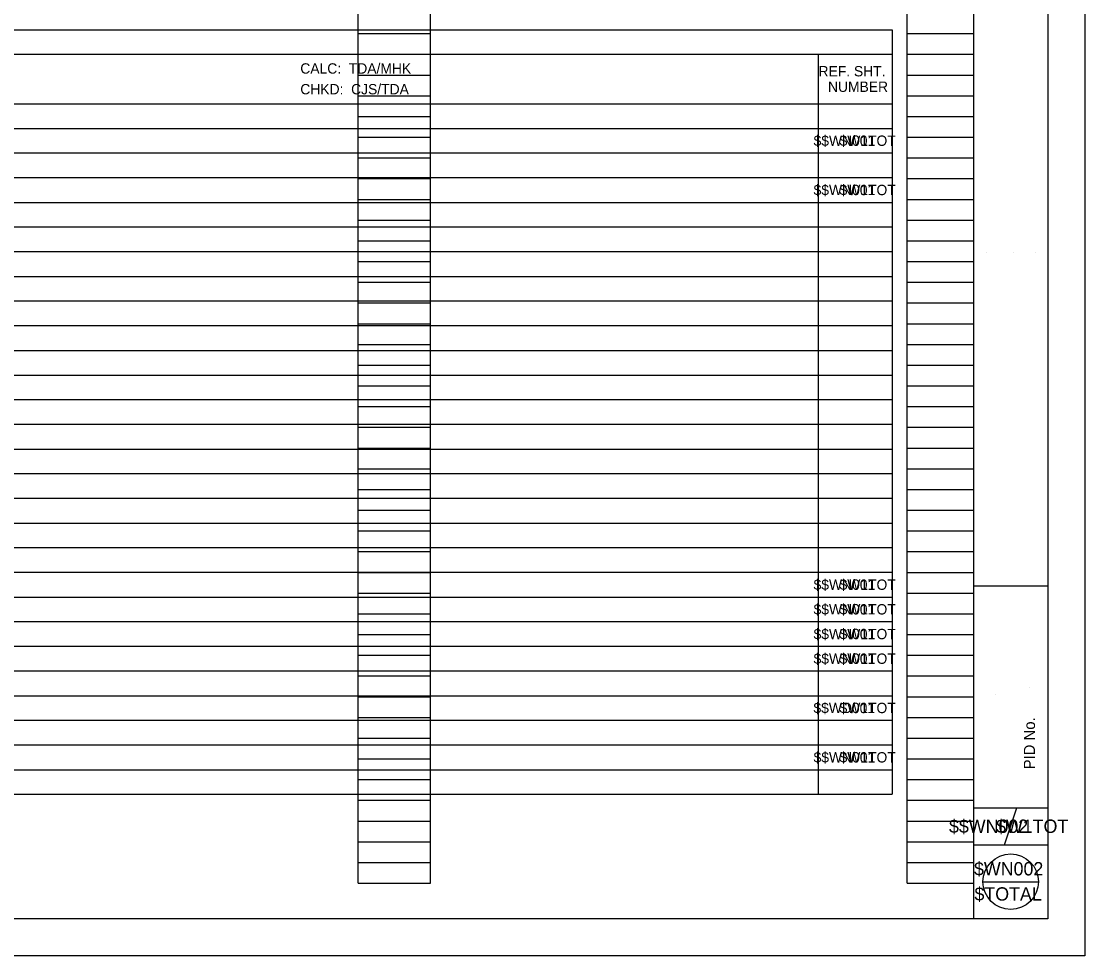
# Model space of a CAD drawing. Extents: x -0.2 to 33.8, y -0.1 to 21.9.
# Drawn here: x 19.4 to 33.78, y -0.13 to 12.49 of the extents above; entities that cross this region are included whole.
import ezdxf

# ---------------------------------------------------------------- set-up
doc = ezdxf.new("R2010")
doc.units = 0
for name, color, linetype in [('SH_Border', 7, 'Continuous'), ('SH_Cut_Line', 7, 'Continuous'), ('SH_Data', 7, 'Continuous'), ('SH_Text', 7, 'Continuous')]:
    doc.layers.add(name, color=color, linetype=linetype)

msp = doc.modelspace()

# ---------------------------------------------------------------- linework, layer by layer
at = {"layer": 'SH_Border'}
for p, q in [((32.275, 0.368), (32.275, 21.368)), ((32.275, 4.868), (33.275, 4.868)), ((32.275, 1.868), (33.275, 1.868)), ((32.692, 1.368), (32.859, 1.868)), ((32.275, 1.368), (33.275, 1.368))]:
    msp.add_line(p, q, dxfattribs=at)
msp.add_lwpolyline([(1.775, 21.368), (33.275, 21.368), (33.275, 0.368), (1.775, 0.368)], close=True, dxfattribs=at)
at = {"layer": 'SH_Cut_Line'}
msp.add_lwpolyline([(-0.225, 21.868), (33.775, 21.868), (33.775, -0.132), (-0.225, -0.132)], close=True, dxfattribs=at)
at = {"layer": 'SH_Data'}
for p, q in [((23.955, 0.848), (23.955, 21.008)), ((24.935, 0.848), (24.935, 21.008)), ((31.375, 0.848), (31.375, 21.008)), ((32.275, 0.848), (32.275, 21.008)), ((2.925, 12.381), (31.175, 12.381)), ((31.175, 12.381), (31.175, 11.381)), ((23.955, 12.328), (24.935, 12.328)), ((31.375, 12.328), (32.275, 12.328)), ((2.925, 12.048), (31.175, 12.048)), ((23.955, 12.048), (24.935, 12.048)), ((30.175, 12.048), (30.175, 11.381)), ((31.375, 12.048), (32.275, 12.048)), ((23.955, 11.768), (24.935, 11.768)), ((31.375, 11.768), (32.275, 11.768)), ((2.925, 11.381), (31.175, 11.381)), ((2.925, 11.381), (31.175, 11.381)), ((23.955, 11.488), (24.935, 11.488)), ((30.175, 11.381), (30.175, 11.048)), ((31.175, 11.381), (31.175, 11.048)), ((31.375, 11.488), (32.275, 11.488)), ((23.955, 11.208), (24.935, 11.208)), ((31.375, 11.208), (32.275, 11.208)), ((2.925, 11.048), (31.175, 11.048)), ((23.955, 10.928), (24.935, 10.928)), ((30.175, 11.048), (30.175, 10.715)), ((31.175, 11.048), (31.175, 10.715)), ((31.375, 10.928), (32.275, 10.928)), ((2.925, 10.715), (31.175, 10.715)), ((23.955, 10.648), (24.935, 10.648)), ((30.175, 10.715), (30.175, 10.382)), ((31.175, 10.715), (31.175, 10.382)), ((31.375, 10.648), (32.275, 10.648)), ((2.925, 10.382), (31.175, 10.382)), ((23.955, 10.368), (24.935, 10.368)), ((30.175, 10.382), (30.175, 10.048)), ((31.175, 10.382), (31.175, 10.048)), ((31.375, 10.368), (32.275, 10.368)), ((23.955, 10.088), (24.935, 10.088)), ((31.375, 10.088), (32.275, 10.088)), ((2.925, 10.048), (31.175, 10.048)), ((30.175, 10.048), (30.175, 9.715)), ((31.175, 10.048), (31.175, 9.715)), ((23.955, 9.808), (24.935, 9.808)), ((31.375, 9.808), (32.275, 9.808)), ((2.925, 9.715), (31.175, 9.715)), ((30.175, 9.715), (30.175, 9.382)), ((31.175, 9.715), (31.175, 9.382)), ((23.955, 9.528), (24.935, 9.528)), ((31.375, 9.528), (32.275, 9.528)), ((2.925, 9.382), (31.175, 9.382)), ((30.175, 9.382), (30.175, 9.048)), ((31.175, 9.382), (31.175, 9.048)), ((32.442, 9.368), (32.442, 9.368)), ((32.817, 9.368), (32.817, 9.368)), ((33.109, 9.368), (33.109, 9.368)), ((23.955, 9.248), (24.935, 9.248)), ((31.375, 9.248), (32.275, 9.248)), ((2.925, 9.048), (31.175, 9.048)), ((23.955, 8.968), (24.935, 8.968)), ((30.175, 9.048), (30.175, 8.715)), ((31.175, 9.048), (31.175, 8.715)), ((31.375, 8.968), (32.275, 8.968)), ((2.925, 8.715), (31.175, 8.715)), ((23.955, 8.688), (24.935, 8.688)), ((30.175, 8.715), (30.175, 8.382)), ((31.175, 8.715), (31.175, 8.382)), ((31.375, 8.688), (32.275, 8.688)), ((2.925, 8.382), (31.175, 8.382)), ((23.955, 8.408), (24.935, 8.408)), ((30.175, 8.382), (30.175, 8.048)), ((31.175, 8.382), (31.175, 8.048)), ((31.375, 8.408), (32.275, 8.408)), ((2.925, 8.048), (31.175, 8.048)), ((23.955, 8.128), (24.935, 8.128)), ((30.175, 8.048), (30.175, 7.715)), ((31.175, 8.048), (31.175, 7.715)), ((31.375, 8.128), (32.275, 8.128)), ((23.955, 7.848), (24.935, 7.848)), ((31.375, 7.848), (32.275, 7.848)), ((2.925, 7.715), (31.175, 7.715)), ((30.175, 7.715), (30.175, 7.382)), ((31.175, 7.715), (31.175, 7.382)), ((23.955, 7.568), (24.935, 7.568)), ((31.375, 7.568), (32.275, 7.568)), ((2.925, 7.382), (31.175, 7.382)), ((30.175, 7.382), (30.175, 7.049)), ((31.175, 7.382), (31.175, 7.049)), ((23.955, 7.288), (24.935, 7.288)), ((31.375, 7.288), (32.275, 7.288)), ((2.925, 7.049), (31.175, 7.049)), ((30.175, 7.049), (30.175, 6.715)), ((31.175, 7.049), (31.175, 6.715)), ((23.955, 7.008), (24.935, 7.008)), ((31.375, 7.008), (32.275, 7.008)), ((2.925, 6.715), (31.175, 6.715)), ((23.955, 6.728), (24.935, 6.728)), ((30.175, 6.715), (30.175, 6.382)), ((31.175, 6.715), (31.175, 6.382)), ((31.375, 6.728), (32.275, 6.728)), ((2.925, 6.382), (31.175, 6.382)), ((23.955, 6.448), (24.935, 6.448)), ((30.175, 6.382), (30.175, 6.049)), ((31.175, 6.382), (31.175, 6.049)), ((31.375, 6.448), (32.275, 6.448)), ((2.925, 6.049), (31.175, 6.049)), ((23.955, 6.168), (24.935, 6.168)), ((30.175, 6.049), (30.175, 5.715)), ((31.175, 6.049), (31.175, 5.715)), ((31.375, 6.168), (32.275, 6.168)), ((23.955, 5.888), (24.935, 5.888)), ((31.375, 5.888), (32.275, 5.888)), ((2.925, 5.715), (31.175, 5.715)), ((23.955, 5.608), (24.935, 5.608)), ((30.175, 5.715), (30.175, 5.382)), ((31.175, 5.715), (31.175, 5.382)), ((31.375, 5.608), (32.275, 5.608)), ((2.925, 5.382), (31.175, 5.382)), ((23.955, 5.328), (24.935, 5.328)), ((30.175, 5.382), (30.175, 5.049)), ((31.175, 5.382), (31.175, 5.049)), ((31.375, 5.328), (32.275, 5.328)), ((2.925, 5.049), (31.175, 5.049)), ((23.955, 5.048), (24.935, 5.048)), ((30.175, 5.049), (30.175, 4.715)), ((31.175, 5.049), (31.175, 4.715)), ((31.375, 5.048), (32.275, 5.048)), ((23.955, 4.768), (24.935, 4.768)), ((31.375, 4.768), (32.275, 4.768)), ((2.925, 4.715), (31.175, 4.715)), ((30.175, 4.715), (30.175, 4.382)), ((31.175, 4.715), (31.175, 4.382)), ((23.955, 4.488), (24.935, 4.488)), ((31.375, 4.488), (32.275, 4.488)), ((2.925, 4.382), (31.175, 4.382)), ((30.175, 4.382), (30.175, 4.049)), ((31.175, 4.382), (31.175, 4.049)), ((23.955, 4.208), (24.935, 4.208)), ((31.375, 4.208), (32.275, 4.208)), ((2.925, 4.049), (31.175, 4.049)), ((30.175, 4.049), (30.175, 3.716)), ((31.175, 4.049), (31.175, 3.716)), ((23.955, 3.928), (24.935, 3.928)), ((31.375, 3.928), (32.275, 3.928)), ((2.925, 3.716), (31.175, 3.716)), ((23.955, 3.648), (24.935, 3.648)), ((30.175, 3.716), (30.175, 3.382)), ((31.175, 3.716), (31.175, 3.382)), ((31.375, 3.648), (32.275, 3.648)), ((33.025, 3.486), (33.025, 3.486)), ((2.925, 3.382), (31.175, 3.382)), ((23.955, 3.368), (24.935, 3.368)), ((30.175, 3.382), (30.175, 3.049)), ((31.175, 3.382), (31.175, 3.049)), ((31.375, 3.368), (32.275, 3.368)), ((32.575, 3.398), (32.575, 3.398)), ((2.925, 3.049), (31.175, 3.049)), ((23.955, 3.088), (24.935, 3.088)), ((30.175, 3.049), (30.175, 2.716)), ((31.175, 3.049), (31.175, 2.716)), ((31.375, 3.088), (32.275, 3.088)), ((23.955, 2.808), (24.935, 2.808)), ((31.375, 2.808), (32.275, 2.808)), ((2.925, 2.716), (31.175, 2.716)), ((30.175, 2.716), (30.175, 2.382)), ((31.175, 2.716), (31.175, 2.382)), ((23.955, 2.528), (24.935, 2.528)), ((31.375, 2.528), (32.275, 2.528)), ((2.925, 2.382), (31.175, 2.382)), ((30.175, 2.382), (30.175, 2.049)), ((31.175, 2.382), (31.175, 2.049)), ((23.955, 2.248), (24.935, 2.248)), ((31.375, 2.248), (32.275, 2.248)), ((2.925, 2.049), (31.175, 2.049)), ((23.955, 1.968), (24.935, 1.968)), ((31.375, 1.968), (32.275, 1.968)), ((23.955, 1.688), (24.935, 1.688)), ((31.375, 1.688), (32.275, 1.688)), ((32.525, 1.618), (32.525, 1.618)), ((33.025, 1.618), (33.025, 1.618)), ((23.955, 1.408), (24.935, 1.408)), ((31.375, 1.408), (32.275, 1.408)), ((23.955, 1.128), (24.935, 1.128)), ((31.375, 1.128), (32.275, 1.128)), ((32.4, 0.868), (33.15, 0.868)), ((32.775, 0.953), (32.775, 0.953)), ((23.955, 0.848), (24.935, 0.848)), ((31.375, 0.848), (32.275, 0.848)), ((32.775, 0.613), (32.775, 0.613))]:
    msp.add_line(p, q, dxfattribs=at)
msp.add_circle((32.775, 0.868), 0.375, dxfattribs=at)

# ---------------------------------------------------------------- texts
for s, height, rotation, p in [('PID No.', 0.15, 90, (33.103, 2.387)), ('$$WN002', 0.18, 360, (31.941, 1.528)), ('$W1TOT', 0.18, 360, (32.577, 1.528)), ('$WN002', 0.18, 360, (32.279, 0.953)), ('$TOTAL', 0.18, 360, (32.285, 0.613))]:
    msp.add_text(s, height=height, rotation=rotation, dxfattribs=at).set_placement(p)
at = {"layer": 'SH_Text'}
for s, p in [('CALC:  TDA/MHK', (23.175, 11.787)), ('REF. SHT.', (30.178, 11.75)), ('CHKD:  CJS/TDA', (23.175, 11.507)), ('NUMBER', (30.306, 11.54)), ('$$WN001', (30.111, 10.811)), ('$W1TOT', (30.462, 10.811)), ('/', (30.621, 10.811)), ('$$WN001', (30.111, 10.145)), ('$W1TOT', (30.462, 10.145)), ('/', (30.621, 10.145)), ('$$WN001', (30.111, 4.812)), ('$W1TOT', (30.462, 4.812)), ('/', (30.621, 4.812)), ('$$WN001', (30.111, 4.479)), ('$W1TOT', (30.462, 4.479)), ('/', (30.621, 4.479)), ('$$WN001', (30.111, 4.145)), ('$W1TOT', (30.462, 4.145)), ('/', (30.621, 4.145)), ('$$WN001', (30.111, 3.812)), ('$W1TOT', (30.462, 3.812)), ('/', (30.621, 3.812)), ('$$WD001', (30.109, 3.146)), ('$W1TOT', (30.462, 3.146)), ('/', (30.621, 3.146)), ('$$WN001', (30.111, 2.479)), ('$W1TOT', (30.462, 2.479)), ('/', (30.621, 2.479))]:
    msp.add_text(s, height=0.14, dxfattribs=at).set_placement(p)

doc.saveas('drawing.dxf')
